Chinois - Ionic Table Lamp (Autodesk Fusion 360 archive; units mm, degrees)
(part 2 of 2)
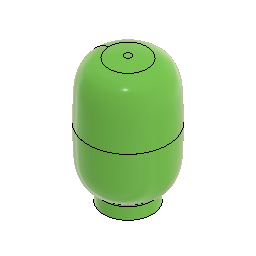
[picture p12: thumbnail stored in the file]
derived_base_feature "Derived Base Feature" bodies "Balon"
work_plane "WorkPlane1" AlongDistance 0
sketch "Sketch1" plane through (0, 0, 0) normal (0, 1, 0) x axis (1, 0, 0)
  line L1 (0, 317.5) -> (0, 2.9083)
  curve K1 (-82.9821, 124.2212) -> (-50.8, 237.8015)
  curve K2 (-51.0925, 237.681) -> (-50.8, 237.8015)
  curve K3 (-51.3855, 237.5558) -> (-51.0925, 237.681)
  curve K4 (-54.7608, 236.0513) -> (-51.3855, 237.5558)
  curve K5 (-57.9615, 234.05) -> (-54.7608, 236.0513)
  curve K6 (-67.2727, 226.749) -> (-57.9615, 234.05)
  curve K7 (-69.0552, 224.2615) -> (-67.2727, 226.749)
  curve K8 (-72.1872, 218.7832) -> (-69.0552, 224.2615)
  curve K9 (-74.1213, 215.1556) -> (-72.1872, 218.7832)
  curve K10 (-78.3031, 204.3965) -> (-74.1213, 215.1556)
  curve K11 (-79.7275, 197.3397) -> (-78.3031, 204.3965)
  curve K12 (-81.3333, 185.4664) -> (-79.7275, 197.3397)
  curve K13 (-81.6254, 178.4008) -> (-81.3333, 185.4664)
  curve K14 (-82.49, 152.2133) -> (-81.6254, 178.4008)
  curve K15 (-82.9821, 136.067) -> (-82.49, 152.2133)
  curve K16 (-82.9821, 124.2212) -> (-82.9821, 136.067)
  curve K17 (50.8, 237.7999) -> (82.9821, 124.2212)
  curve K18 (82.9821, 140.3031) -> (82.9821, 124.2212)
  curve K19 (81.9353, 169.4257) -> (82.9821, 140.3031)
  curve K20 (81.3621, 183.6489) -> (81.9353, 169.4257)
  curve K21 (80.9478, 189.8724) -> (81.3621, 183.6489)
  curve K22 (77.8147, 206.9858) -> (80.9478, 189.8724)
  curve K23 (74.9652, 213.2153) -> (77.8147, 206.9858)
  curve K24 (69.4688, 224.1531) -> (74.9652, 213.2153)
  curve K25 (67.2512, 226.458) -> (69.4688, 224.1531)
  curve K26 (61.5696, 231.3138) -> (67.2512, 226.458)
  curve K27 (57.377, 234.6711) -> (61.5696, 231.3138)
  curve K28 (52.0556, 237.2628) -> (57.377, 234.6711)
  curve K29 (51.4313, 237.5413) -> (52.0556, 237.2628)
  curve K30 (50.8, 237.7999) -> (51.4313, 237.5413)
  line L2 (-50.8, 317.5) -> (-50.8, 237.8015)
  line L3 (50.8, 317.5) -> (50.8, 237.7999)
  line L4 (-19.0713, 6.7501) -> (-19.0713, 6.7501)
  curve K31 (82.9821, 124.1958) -> (40.1509, 7.3012)
  curve K32 (41.8198, 7.6176) -> (40.1509, 7.3012)
  curve K33 (43.2113, 8.0663) -> (41.8198, 7.6176)
  curve K34 (47.0139, 9.2854) -> (43.2113, 8.0663)
  curve K35 (47.3314, 9.3805) -> (47.0139, 9.2854)
  curve K36 (50.1192, 10.3272) -> (47.3314, 9.3805)
  curve K37 (51.833, 11.0085) -> (50.1192, 10.3272)
  curve K38 (57.8313, 14.1895) -> (51.833, 11.0085)
  curve K39 (61.4491, 17.0488) -> (57.8313, 14.1895)
  curve K40 (66.8203, 21.5867) -> (61.4491, 17.0488)
  curve K41 (68.5372, 23.5528) -> (66.8203, 21.5867)
  curve K42 (71.2201, 27.8971) -> (68.5372, 23.5528)
  curve K43 (74.7424, 33.8984) -> (71.2201, 27.8971)
  curve K44 (78.2342, 44.8406) -> (74.7424, 33.8984)
  curve K45 (79.6792, 50.3463) -> (78.2342, 44.8406)
  curve K46 (81.3558, 63.5576) -> (79.6792, 50.3463)
  curve K47 (81.6386, 70.4415) -> (81.3558, 63.5576)
  curve K48 (82.4897, 96.2198) -> (81.6386, 70.4415)
  curve K49 (82.9814, 112.3523) -> (82.4897, 96.2198)
  curve K50 (82.9821, 124.1958) -> (82.9814, 112.3523)
  curve K51 (-40.1501, 7.301) -> (-82.9821, 124.1958)
  curve K52 (-82.9813, 110.5256) -> (-82.9821, 124.1958)
  curve K53 (-82.2545, 88.8594) -> (-82.9813, 110.5256)
  curve K54 (-81.6277, 70.519) -> (-82.2545, 88.8594)
  curve K55 (-81.3572, 64.3441) -> (-81.6277, 70.519)
  curve K56 (-79.4149, 46.8924) -> (-81.3572, 64.3441)
  curve K57 (-76.5204, 38.9768) -> (-79.4149, 46.8924)
  curve K58 (-73.5142, 32.2947) -> (-76.5204, 38.9768)
  curve K59 (-72.5556, 30.3818) -> (-73.5142, 32.2947)
  curve K60 (-69.7914, 25.3691) -> (-72.5556, 30.3818)
  curve K61 (-68.3824, 23.4028) -> (-69.7914, 25.3691)
  curve K62 (-64.5419, 19.5456) -> (-68.3824, 23.4028)
  curve K63 (-62.3002, 17.7646) -> (-64.5419, 19.5456)
  curve K64 (-53.6583, 11.1976) -> (-62.3002, 17.7646)
  curve K65 (-49.6968, 10.1396) -> (-53.6583, 11.1976)
  curve K66 (-43.4141, 8.1331) -> (-49.6968, 10.1396)
  curve K67 (-41.9704, 7.6516) -> (-43.4141, 8.1331)
  curve K68 (-40.1963, 7.3098) -> (-41.9704, 7.6516)
  curve K69 (-40.1732, 7.3054) -> (-40.1963, 7.3098)
  curve K70 (-40.1501, 7.301) -> (-40.1732, 7.3054)
  line L5 (-82.9821, 124.1958) -> (-82.9821, 124.2212)
  line L6 (82.9821, 124.2212) -> (82.9821, 124.1958)
  line L7 (0, 317.5) -> (-50.8, 317.5)
  line L8 (7.2015, 3.048) -> (0, 3.048)
  line L9 (0, 3.048) -> (-7.2015, 3.048)
  arc A1 centre (0, 188.595) radius 185.6867 clockwise from (-7.2015, 3.048) to (-40.1502, 7.301)
  arc A2 centre (0, 188.595) radius 185.6867 clockwise from (40.151, 7.3012) to (7.2015, 3.048)
  point P38 (-40.1502, 7.301)
  point P43 (40.1509, 7.3012)
  point P62 (-40.1501, 7.301)
  point P81 (40.151, 7.3012)
  point P84 (0, 3.048)
  vertical L1
  horizontal L4
  coincident P38 K51
  symmetric L1 A1 A2
  coincident A2 P43
  coincident A1 P62
  coincident K31 P81
  perpendicular L2 L7
  horizontal L8
  coincident L1 P84
  horizontal L9
revolve "Revolve1" sketch "Sketch1" AlongAngle 360
shell "Shell1" innerThickness 3.81
fillet "Fillet1" radius 6.35
offset_faces "OffsetFaces1" distance -50.8
move "Move1"
move "Move2"
component_from_bodies "Body->Comp1"
component_from_bodies "Body->Comp2"
sketch "Sketch2" plane through (0, 0, 0) normal (0, 1, 0) x axis (1, 0, 0)
  line L1 (-85.5221, 124.2212) -> (-85.5221, 124.1961)
  curve K1 (-58.9057, 236.4383) -> (-50.8, 241.7989)
  curve K2 (-50.8, 241.554) -> (-50.8, 241.7989)
  curve K3 (-50.904, 240.933) -> (-50.8, 241.554)
  curve K4 (-51.2936, 240.2837) -> (-50.904, 240.933)
  curve K5 (-51.734, 239.7561) -> (-51.2936, 240.2837)
  curve K6 (-53.328, 238.5038) -> (-51.734, 239.7561)
  curve K7 (-54.0892, 238.1997) -> (-53.328, 238.5038)
  curve K8 (-58.9057, 236.4383) -> (-54.0892, 238.1997)
  curve K9 (-89.3309, 124.2212) -> (-58.9057, 236.4383)
  curve K10 (-62.6336, 234.9735) -> (-58.9057, 236.4383)
  curve K11 (-65.581, 233.1032) -> (-62.6336, 234.9735)
  curve K12 (-73.0224, 227.0019) -> (-65.581, 233.1032)
  curve K13 (-74.8981, 224.836) -> (-73.0224, 227.0019)
  curve K14 (-78.1104, 219.6097) -> (-74.8981, 224.836)
  curve K15 (-80.2663, 215.561) -> (-78.1104, 219.6097)
  curve K16 (-84.0943, 205.8277) -> (-80.2663, 215.561)
  curve K17 (-85.4655, 200.1154) -> (-84.0943, 205.8277)
  curve K18 (-87.4092, 188.5789) -> (-85.4655, 200.1154)
  curve K19 (-87.7349, 182.3889) -> (-87.4092, 188.5789)
  curve K20 (-88.4233, 165.9645) -> (-87.7349, 182.3889)
  curve K21 (-89.328, 138.6964) -> (-88.4233, 165.9645)
  curve K22 (-89.3309, 124.2212) -> (-89.328, 138.6964)
  line L2 (-89.3309, 124.1958) -> (-89.3309, 124.2212)
  curve K23 (-46.5001, 7.301) -> (-89.3309, 124.1958)
  curve K24 (-89.3314, 112.4293) -> (-89.3309, 124.1958)
  curve K25 (-88.8181, 95.3068) -> (-89.3314, 112.4293)
  curve K26 (-88.346, 81.2892) -> (-88.8181, 95.3068)
  curve K27 (-88.0298, 70.4902) -> (-88.346, 81.2892)
  curve K28 (-87.1514, 58.328) -> (-88.0298, 70.4902)
  curve K29 (-86.3326, 50.6119) -> (-87.1514, 58.328)
  curve K30 (-81.0932, 33.6688) -> (-86.3326, 50.6119)
  curve K31 (-77.3163, 27.4309) -> (-81.0932, 33.6688)
  curve K32 (-74.8955, 23.6666) -> (-77.3163, 27.4309)
  curve K33 (-73.5108, 22.0741) -> (-74.8955, 23.6666)
  curve K34 (-70.2346, 19.0457) -> (-73.5108, 22.0741)
  curve K35 (-64.8094, 14.3548) -> (-70.2346, 19.0457)
  curve K36 (-56.6696, 10.3041) -> (-64.8094, 14.3548)
  curve K37 (-54.0053, 9.483) -> (-56.6696, 10.3041)
  curve K38 (-49.1487, 7.9411) -> (-54.0053, 9.483)
  curve K39 (-48.3482, 7.6526) -> (-49.1487, 7.9411)
  curve K40 (-46.5001, 7.301) -> (-48.3482, 7.6526)
  line L3 (0, 266.7) -> (0, 0)
  line L4 (0, 3.048) -> (-7.7894, 3.048)
  line L5 (-50.8, 266.7) -> (-50.8, 241.7989)
  line L6 (0, 266.7) -> (-50.8, 266.7)
  arc A1 centre (-6.9779, 188.7329) radius 185.6867 clockwise from (-7.7894, 3.048) to (-46.5001, 7.301)
  point P1 (0, 0)
  point P44 (0, 0)
  point P46 (0, 3.048)
  point P5 (-50.8, 241.554)
  point P49 (0, 266.7)
  coincident P1 P44
  coincident L3 P46
  coincident P5 L5
  coincident L3 P49
revolve "Revolve2" sketch "Sketch2" AlongAngle 360 bodies "Balon v3"
shell "Shell2" innerThickness 3.81
component_from_bodies "Body->Comp3"
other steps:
base_feature "Base Feature1" bodies "Balon"
base_feature "Base Feature1" bodies "Balon v3"
base_feature "Base Feature1" bodies "Balon v2"
create_component "CreateComponent1"
remove_body "RemoveBody1"
create_component "CreateComponent2"
remove_body "RemoveBody2"
create_component "CreateComponent3"
remove_body "RemoveBody3"
named bodies: "Balon", "Balon v2", "Balon v3"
